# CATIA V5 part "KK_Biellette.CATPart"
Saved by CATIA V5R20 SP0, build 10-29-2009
Part number: Biellette
Bounding box of the stored display mesh (mm): x 10 to 15, y 78 to 142, z -7 to 7
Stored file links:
  G:\Khaled_CFAO_2011\ST2M\ST2M_GR2\aandujar\Khaled\CAD_thinkMOTION\KK_Biellette.CATPart
  G:\Khaled_CFAO_2011\ST2M\ST2M_GR2\aandujar\Khaled\CAD_thinkMOTION\KK_Aandujar.CATProduct
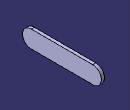
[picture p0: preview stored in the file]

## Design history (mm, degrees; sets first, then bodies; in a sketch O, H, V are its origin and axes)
WSupportSet1: ActiveGrid {3dwsupport RefPoint {point stored without definition}, 3DWOS ({wsupport Support xy-plane, RefPoint {3dwsupport}, GridIn {cartgrid Value 100, Stepbid1 0, Value 100, Stepbid2 0, Direction (1, 0, 0)}, GeometricData ({line type PtDir, Direction (1, 0, 0), Support xy-plane}; {line type PtDir, Direction (0, 1, 0), Support yz-plane})}; {wsupport Support yz-plane, RefPoint {3dwsupport}, GridIn {cartgrid Value 100, Stepbid1 0, Value 100, Stepbid2 0, Direction (0, 1, 0)}, GeometricData ({line type PtDir, Direction (0, 1, 0), Support yz-plane}; {line type PtDir, Direction (0, 0, 1), Support zx-plane})}; {wsupport Support zx-plane, RefPoint {3dwsupport}, GridIn {cartgrid Value 100, Stepbid1 0, Value 100, Stepbid2 0, Direction (0, 0, 1)}, GeometricData ({line type PtDir, Direction (0, 0, 1), Support zx-plane}; {line type PtDir, Direction (1, 0, 0), Support xy-plane})}), GeometricData ({line type PtDir, RefPoint {point stored without definition}, Direction (1, 0, 0), Support xy-plane}; {line type PtDir, RefPoint {point stored without definition}, Direction (0, 1, 0), Support yz-plane}; {line type PtDir, RefPoint {point stored without definition}, Direction (0, 0, 1), Support zx-plane})}
Set1
  Sketch1 on Plane1, origin (12.5, 0, 0), H (0, 1, 0), V (0, 0, 1)
    construction line L1 (85, 0) -> (135, 0)
    point P1 (85, 0)
    point P2 (135, 0)
    line L2 (85, 7) -> (135, 7)
    line L3 (135, -7) -> (85, -7)
    arc A1 centre (135, 0) radius 7 from (135, 7) to (135, -7) cw
    arc A2 centre (85, 0) radius 7 from (85, -7) to (85, 7) cw
    reference projected point E1 (85, 0) from Point1
    reference projected point E2 (135, 0) from Point2
    distance L1 L2 = 7
    horizontal: L1 H
    tangency: A1 L2, A2 L2, A1 L3, A2 L3
    coincidence: E1 P1, E2 P2
Set2
  Plane1 "Plan.Ref5": linked copy from another document
  Point1: linked copy from another document
  Point2: linked copy from another document
Body1 (main body)
  Pad1: profile Sketch1, direction (1, 0, 0), length 2.5
  Sketch2 on start face of Pad1, origin (12.5, 0, 0), H (0, -1, 0), V (0, 0, 1)
    circle A1 centre (-135, 0) radius 2.5
    point P1 (-135, 0)
    reference projected point E1 (-135, 0) from Point2
    radius A1 = 2.5
    coincidence: E1 P1
  Pad2: profile Sketch2, direction (-1, 0, 0), length 2.5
